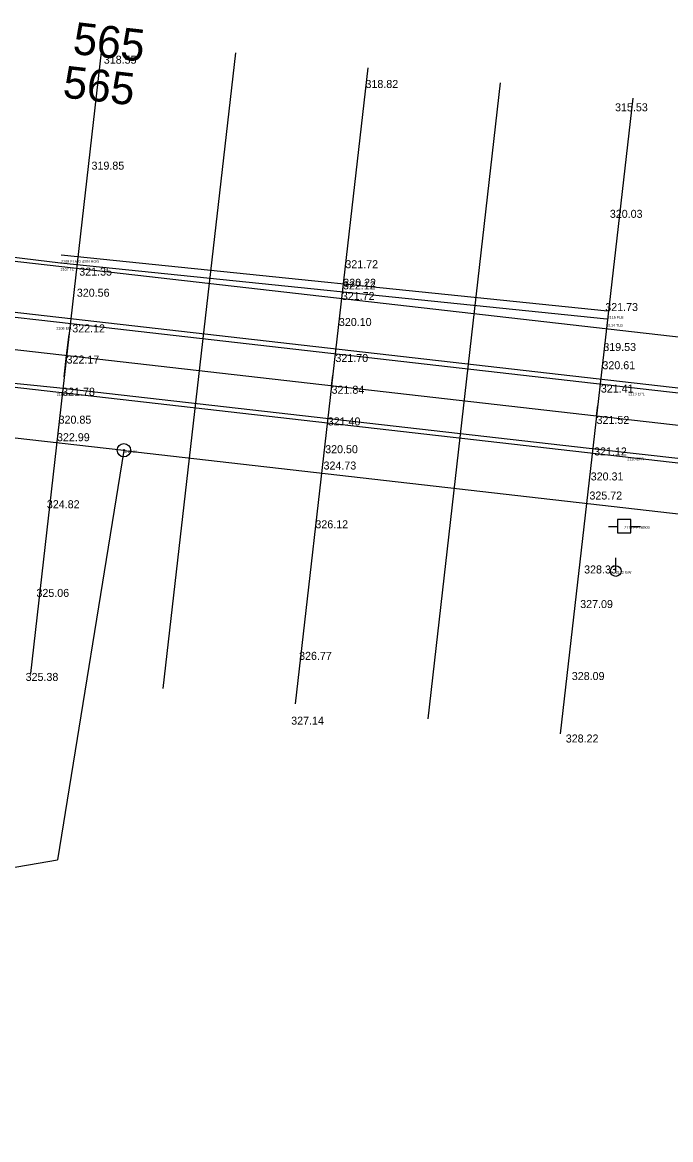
# Model space of a CAD drawing. Extents: x 49683 to 58852, y 49525 to 54803.
# Drawn here: x 57276.3 to 57519.5, y 53727.3 to 54146.3 of the extents above; entities that cross this region are included whole.
import ezdxf

# ---------------------------------------------------------------- set-up
doc = ezdxf.new("R2010")
doc.units = 0
for name, color, linetype in [('Level 1', 7, 'Continuous'), ('Level 11', 7, 'Continuous'), ('Level 12', 7, 'Continuous'), ('Level 13', 7, 'Continuous'), ('Level 20', 7, 'Continuous'), ('Level 21', 7, 'Continuous'), ('Level 29', 7, 'Continuous'), ('Level 3', 7, 'Continuous'), ('Level 32', 7, 'Continuous'), ('Level 50', 7, 'Continuous'), ('Level 53', 7, 'Continuous'), ('Level 58', 7, 'Continuous'), ('Level 59', 7, 'Continuous'), ('Level 61', 7, 'Continuous'), ('Level 62', 7, 'Continuous'), ('Level 8', 7, 'Continuous'), ('Level 9', 7, 'Continuous')]:
    doc.layers.add(name, color=color, linetype=linetype)

# ---------------------------------------------------------------- blocks, each defined once
blk = doc.blocks.new('IP')
at = {"layer": 'Level 12'}
for radius in [2.5, 0.25]:
    blk.add_circle((0, 0), radius, dxfattribs=at)
blk = doc.blocks.new('PP')
at = {"layer": 'Level 9'}
for p, q in [((2.53, 2.45), (-2.47, 2.45)), ((-2.47, 2.45), (-2.47, -2.55)), ((2.53, -2.55), (2.53, 2.45)), ((-5.91, -0.11), (-2.44, -0.11)), ((-2.47, -2.55), (2.53, -2.55)), ((2.45, -0.11), (6.09, -0.11))]:
    blk.add_line(p, q, dxfattribs=at)
blk = doc.blocks.new('GW')
at = {"layer": 'Level 9'}
blk.add_line((0, 0), (0, 5), dxfattribs=at)
blk.add_circle((0, 0), 2, dxfattribs=at)

msp = doc.modelspace()

# ---------------------------------------------------------------- linework, layer by layer
at = {"layer": 'Level 1'}
for p, q in [((56981.58, 54056.82), (58783.3, 53851.37)), ((57292.96, 54021.32), (57293.87, 54029.26)), ((57292.06, 54013.37), (57292.96, 54021.32)), ((57392.32, 54009.99), (57392.77, 54013.96)), ((57491.68, 53998.66), (57492.13, 54002.63))]:
    msp.add_line(p, q, dxfattribs=at)
at = {"layer": 'Level 11'}
for p, q in [((57155.88, 54072.62), (57290.67, 54056.11)), ((57290.67, 54056.11), (57495.57, 54035.12))]:
    msp.add_line(p, q, dxfattribs=at)
at = {"layer": 'Level 12'}
for p in [(57314.41, 53985.66), (56690.99, 53727.29)]:
    msp.add_line(p, (57289.55, 53832.27), dxfattribs=at)
at = {"layer": 'Level 13'}
for p, q in [((57134.79, 54072.57), (58787.04, 53884.15)), ((57314.41, 53985.66), (56917.82, 54030.88)), ((57314.41, 53985.66), (58779.57, 53818.58))]:
    msp.add_line(p, q, dxfattribs=at)
at = {"layer": 'Level 20'}
for p, q in [((56983.17, 54070.73), (58784.89, 53865.28)), ((56980, 54042.91), (58781.72, 53837.46))]:
    msp.add_line(p, q, dxfattribs=at)
at = {"layer": 'Level 29'}
for p, q in [((56981.58, 54056.82), (58783.3, 53851.37)), ((57292.97, 54021.32), (57293.87, 54029.26)), ((57392.32, 54009.99), (57392.77, 54013.96)), ((57491.68, 53998.66), (57492.13, 54002.63))]:
    msp.add_line(p, q, dxfattribs=at)
at = {"layer": 'Level 3'}
for p, q in [((57169.61, 54047.04), (57289.1, 54034.02)), ((57289.1, 54034.02), (57503.69, 54009.45)), ((57167.04, 54022.13), (57289.26, 54009.3)), ((57289.26, 54009.3), (57503.24, 53984.99)), ((57503.69, 54009.45), (57780.7, 53977.52)), ((57503.24, 53984.99), (57776.18, 53954.21))]:
    msp.add_line(p, q, dxfattribs=at)
at = {"layer": 'Level 50'}
for p, q in [((57306.56, 54140.54), (57279.37, 53902.09)), ((57356.24, 54134.88), (57329.05, 53896.42)), ((57405.92, 54129.21), (57378.73, 53890.76)), ((57455.6, 54123.55), (57428.41, 53885.09)), ((57505.28, 54117.88), (57478.08, 53879.43))]:
    msp.add_line(p, q, dxfattribs=at)
at = {"layer": 'Level 8'}
msp.add_line((57290.87, 54059.1), (57495.84, 54038.11), dxfattribs=at)

# ---------------------------------------------------------------- block references
at = {"layer": 'Level 12'}
msp.add_blockref('IP', (57314.44, 53985.83), dxfattribs=at)
at = {"layer": 'Level 9'}
for name, p in [('PP', (57502.09, 53957.35)), ('GW', (57498.91, 53940.5))]:
    msp.add_blockref(name, p, dxfattribs=at)

# ---------------------------------------------------------------- texts
at = {"layer": 'Level 21'}
for p in [(57294.95, 54134.49), (57291.18, 54118.14)]:
    msp.add_text('565', height=12, rotation=353.4944, dxfattribs=at).set_placement(p)
at = {"layer": 'Level 32'}
for s, p in [('318.55', (57306.89, 54130.76)), ('318.82', (57405.04, 54121.65)), ('315.53', (57498.65, 54112.91)), ('319.85', (57302.29, 54091.03)), ('320.03', (57496.69, 54072.96)), ('321.72', (57397.49, 54054.07)), ('321.35', (57297.69, 54051.29)), ('322.12', (57396.6, 54046.12)), ('320.22', (57396.71, 54047.11)), ('320.56', (57296.78, 54043.38)), ('321.72', (57396.16, 54042.14)), ('321.73', (57494.98, 54038)), ('320.10', (57395.07, 54032.4)), ('322.12', (57295.07, 54030)), ('319.53', (57494.25, 54023.02)), ('322.17', (57292.92, 54018.32)), ('321.70', (57393.77, 54018.9)), ('320.61', (57493.91, 54016.19)), ('321.84', (57392.32, 54006.99)), ('321.41', (57493.32, 54007.44)), ('321.78', (57291.28, 54006.24)), ('320.85', (57289.94, 53995.77)), ('321.40', (57390.88, 53995.11)), ('321.52', (57491.7, 53995.67)), ('322.99', (57289.34, 53989.2)), ('320.50', (57389.92, 53984.7)), ('321.12', (57490.79, 53983.86)), ('324.73', (57389.31, 53978.58)), ('320.31', (57489.52, 53974.49)), ('325.72', (57489.04, 53967.33)), ('324.82', (57285.54, 53964.07)), ('326.12', (57386.25, 53956.55)), ('328.33', (57487.04, 53939.6)), ('325.06', (57281.63, 53930.81)), ('327.09', (57485.58, 53926.64)), ('326.77', (57380.14, 53907.21)), ('325.38', (57277.57, 53899.31)), ('328.09', (57482.43, 53899.64)), ('327.14', (57377.18, 53882.91)), ('328.22', (57480.16, 53876.22))]:
    msp.add_text(s, height=3, dxfattribs=at).set_placement(p)
at = {"layer": 'Level 53'}
for s, p in [('2106 EPL ', (57289.1, 54031.02)), ('2109 EPR ', (57289.26, 54006.3)), ('2113 EPL ', (57503.69, 54006.45)), ('2110 EPR ', (57503.24, 53981.99))]:
    msp.add_text(s, height=1, dxfattribs=at).set_placement(p)
at = {"layer": 'Level 58'}
for s, p in [('2108 FLA O 40IN HOG ', (57290.87, 54056.1)), ('2115 FLB ', (57495.84, 54035.11))]:
    msp.add_text(s, height=1, dxfattribs=at).set_placement(p)
at = {"layer": 'Level 59'}
for s, p in [('2111 PP 08909 ', (57502.09, 53956.35)), ('2112 GW ', (57498.91, 53939.5))]:
    msp.add_text(s, height=1, dxfattribs=at).set_placement(p)
at = {"layer": 'Level 61'}
for s, p in [('2107 TL ', (57290.67, 54053.11)), ('2114 TLB ', (57495.57, 54032.12))]:
    msp.add_text(s, height=1, dxfattribs=at).set_placement(p)
at = {"layer": 'Level 62'}
msp.add_text('1722 IP ', height=1, dxfattribs=at).set_placement((57314.44, 53984.83))

doc.saveas('drawing.dxf')
